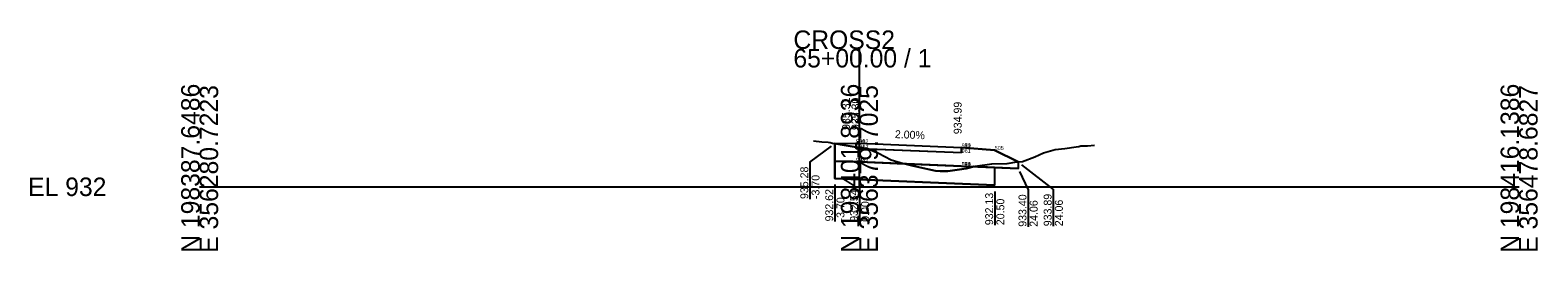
# Model space of a CAD drawing. Extents: x -26 to 203, y -10 to 14021.
# Drawn here: x -25.7 to 202.8, y 5990.3 to 6023.7 of the extents above; entities that cross this region are included whole.
import ezdxf

# ---------------------------------------------------------------- set-up
doc = ezdxf.new("R2010")
doc.units = 0
for name, color, linetype in [('Default', 7, 'Continuous'), ('P_E_XS_Ground', 7, 'Continuous'), ('P_XS', 7, 'Continuous'), ('P_XS_Bold', 7, 'Continuous'), ('P_XS_EAR_CommonGrnd', 7, 'Continuous'), ('P_XS_Lane', 7, 'Continuous'), ('P_XS_Rock', 7, 'Continuous')]:
    doc.layers.add(name, color=color, linetype=linetype)

msp = doc.modelspace()

# ---------------------------------------------------------------- linework, layer by layer
at = {"layer": 'Default'}
for p, q in [((100, 6000), (100, 6020.87)), ((0, 6000), (100, 6000)), ((100, 6000), (200, 6000))]:
    msp.add_line(p, q, dxfattribs=at)
at = {"layer": 'P_E_XS_Ground'}
for p, q in [((93.04, 6006.96), (94.32, 6006.81)), ((94.32, 6006.81), (95.26, 6006.75)), ((95.26, 6006.75), (95.57, 6006.71)), ((95.57, 6006.71), (95.91, 6006.63)), ((95.91, 6006.63), (97.7, 6006.32)), ((97.7, 6006.32), (99.2, 6006.06)), ((99.2, 6006.06), (100.2, 6005.89)), ((100.2, 6005.89), (101.18, 6005.81)), ((131.13, 6005.8), (132.84, 6006.03)), ((132.84, 6006.03), (133.24, 6006.11)), ((133.24, 6006.11), (133.55, 6006.19)), ((133.55, 6006.19), (134.57, 6006.19)), ((134.57, 6006.19), (135.62, 6006.31)), ((101.18, 6005.81), (102.92, 6005.08)), ((102.92, 6005.08), (104.84, 6004.07)), ((104.84, 6004.07), (106.7, 6003.53)), ((122.42, 6003.51), (123.87, 6003.78)), ((123.87, 6003.78), (124.73, 6003.84)), ((124.73, 6003.84), (126.59, 6004.52)), ((126.59, 6004.52), (127.91, 6005.13)), ((127.91, 6005.13), (128.96, 6005.43)), ((128.96, 6005.43), (129.68, 6005.63)), ((129.68, 6005.63), (131.13, 6005.8)), ((106.7, 6003.53), (108.11, 6003.17)), ((108.11, 6003.17), (110.38, 6002.69)), ((110.38, 6002.69), (111.56, 6002.4)), ((111.56, 6002.4), (112.27, 6002.38)), ((112.27, 6002.38), (113.43, 6002.38)), ((113.43, 6002.38), (115.16, 6002.62)), ((115.16, 6002.62), (116.19, 6002.77)), ((116.19, 6002.77), (117.56, 6003.13)), ((117.56, 6003.13), (120.07, 6003.47)), ((120.07, 6003.47), (122.42, 6003.51))]:
    msp.add_line(p, q, dxfattribs=at)
at = {"layer": 'P_XS'}
for p, q in [((96.3, 6006.56), (96.3, 6003.9)), ((99.5, 6006.61), (99.5, 6005.78)), ((115.5, 6005.14), (115.5, 6005.97)), ((96.3, 6003.9), (100, 6003.76)), ((96.3, 6003.9), (96.3, 6001.24)), ((99.5, 6005.78), (100, 6005.76)), ((115.5, 6005.14), (100, 6005.76)), ((115.5, 6003.14), (100, 6003.76)), ((124.06, 6003.79), (124.06, 6002.79)), ((115.5, 6003.14), (124.06, 6002.79)), ((120.5, 6002.94), (120.5, 6000.27)), ((96.3, 6001.24), (120.5, 6000.27))]:
    msp.add_line(p, q, dxfattribs=at)
at = {"layer": 'P_XS_EAR_CommonGrnd'}
for points in [[(96.3, 6006.56), (99.5, 6006.61), (99.5, 6006.01), (99.2, 6006.06), (97.7, 6006.32)], [(102.92, 6005.08), (104.84, 6004.07), (106.7, 6003.53), (106.91, 6003.48), (100, 6003.76), (96.3, 6003.9), (96.3, 6006.56), (97.7, 6006.32), (99.2, 6006.06), (99.5, 6006.01), (99.5, 6005.78), (100, 6005.76), (101.44, 6005.7)], [(115.5, 6005.14), (101.44, 6005.7), (101.18, 6005.81), (100.2, 6005.89), (99.5, 6006.01), (99.5, 6006.61), (100, 6006.59), (115.5, 6005.97)], [(100.2, 6005.89), (101.18, 6005.81), (101.44, 6005.7), (100, 6005.76), (99.5, 6005.78), (99.5, 6006.01)], [(115.5, 6005.14), (101.44, 6005.7), (102.92, 6005.08), (104.84, 6004.07), (106.7, 6003.53), (106.91, 6003.48), (115.5, 6003.14), (117.31, 6003.06), (117.56, 6003.13), (120.07, 6003.47), (122.42, 6003.51), (123.87, 6003.78), (124.06, 6003.79), (120.5, 6005.57), (115.5, 6005.97)], [(108.11, 6003.17), (110.38, 6002.69), (111.56, 6002.4), (112.27, 6002.38), (113.43, 6002.38), (115.16, 6002.62), (116.19, 6002.77), (117.31, 6003.06), (120.5, 6002.94), (120.5, 6000.27), (96.3, 6001.24), (96.3, 6003.9), (100, 6003.76), (106.91, 6003.48)], [(124.06, 6003.79), (124.06, 6002.79), (120.5, 6002.94), (117.31, 6003.06), (117.56, 6003.13), (120.07, 6003.47), (122.42, 6003.51), (123.87, 6003.78)], [(115.5, 6003.14), (117.31, 6003.06), (116.19, 6002.77), (115.16, 6002.62), (113.43, 6002.38), (112.27, 6002.38), (111.56, 6002.4), (110.38, 6002.69), (108.11, 6003.17), (106.91, 6003.48)]]:
    msp.add_lwpolyline(points, close=True, dxfattribs=at)
at = {"layer": 'P_XS_Lane'}
for p, q in [((96.3, 6006.56), (99.5, 6006.61)), ((99.5, 6006.61), (100, 6006.59)), ((100, 6006.59), (115.5, 6005.97)), ((115.5, 6005.97), (120.5, 6005.57)), ((120.5, 6005.57), (124.06, 6003.79))]:
    msp.add_line(p, q, dxfattribs=at)
at = {"layer": 'P_XS_Rock'}
for p, q in [((92.5, 6003.75), (95.78, 6006.17)), ((92.5, 6003.75), (92.5, 5998.15)), ((125.57, 5999.64), (124.3, 6002.3)), ((129.39, 5999.63), (124.64, 6003.34)), ((96.28, 6000.35), (96.28, 5994.76)), ((100.02, 6000.29), (100.02, 5994.7)), ((120.52, 5999.3), (120.52, 5994.19)), ((125.57, 5999.64), (125.57, 5993.94)), ((129.39, 5999.63), (129.39, 5994.03))]:
    msp.add_line(p, q, dxfattribs=at)

# ---------------------------------------------------------------- texts
at = {"layer": 'Default'}
for s, p in [('CROSS2', (90, 6020.87)), ('65+00.00 / 1', (90, 6018.07)), ('EL 932', (-26, 5998.6))]:
    msp.add_text(s, height=2.8, dxfattribs=at).set_placement(p)
for s, p in [('N 198387.6486', (0, 5990)), ('E 356280.7223', (2.8, 5990)), ('N 198401.8936', (100, 5990)), ('E 356379.7025', (102.8, 5990)), ('N 198416.1386', (200, 5990)), ('E 356478.6827', (202.8, 5990))]:
    msp.add_text(s, height=2.8, rotation=90, dxfattribs=at).set_placement(p)
at = {"layer": 'P_XS_Bold'}
for s, p in [('951', (99.5, 6006.61)), ('9', (99.5, 6006.61)), ('900', (99.5, 6006.61)), ('961', (99.5, 6005.78)), ('952', (100, 6006.59)), ('952', (100, 6006.59)), ('962', (100, 6005.76)), ('962', (100, 6005.76)), ('951', (115.5, 6005.97)), ('9', (115.5, 6005.97)), ('900', (115.5, 6005.97)), ('910', (115.5, 6005.97)), ('505', (120.5, 6005.57)), ('971', (99.5, 6003.78)), ('998', (99.5, 6003.78)), ('972', (100, 6003.76)), ('972', (100, 6003.76)), ('540', (115.5, 6003.14)), ('961', (115.5, 6005.14)), ('971', (115.5, 6003.14)), ('998', (115.5, 6003.14))]:
    msp.add_text(s, height=0.6, dxfattribs=at).set_placement(p)
at = {"layer": 'P_XS_Rock'}
for s, rotation, p in [('935.31', 90, (98.57, 6008.61)), ('935.30', 90, (100, 6008.59)), ('935.30', 90, (100, 6008.59)), ('935.30', 90, (100, 6008.59)), ('935.30', 90, (100, 6008.59)), ('934.99', 90, (115.5, 6007.97)), ('2.00%', 357.7094, (105.36, 6007.38)), ('935.28', 90, (92.25, 5998.15)), ('-3.70', 90, (93.95, 5998.15)), ('932.62', 90, (96.03, 5994.76)), ('932.54', 90, (99.77, 5994.7)), ('932.13', 90, (120.27, 5994.19)), ('-3.70', 90, (97.73, 5994.76)), ('0.00', 90, (101.47, 5994.7)), ('20.50', 90, (121.97, 5994.19)), ('933.40', 90, (125.32, 5993.95)), ('24.06', 90, (127.02, 5993.95)), ('933.89', 90, (129.14, 5994.03)), ('24.06', 90, (130.84, 5994.03))]:
    msp.add_text(s, height=1.2, rotation=rotation, dxfattribs=at).set_placement(p)

doc.saveas('drawing.dxf')
